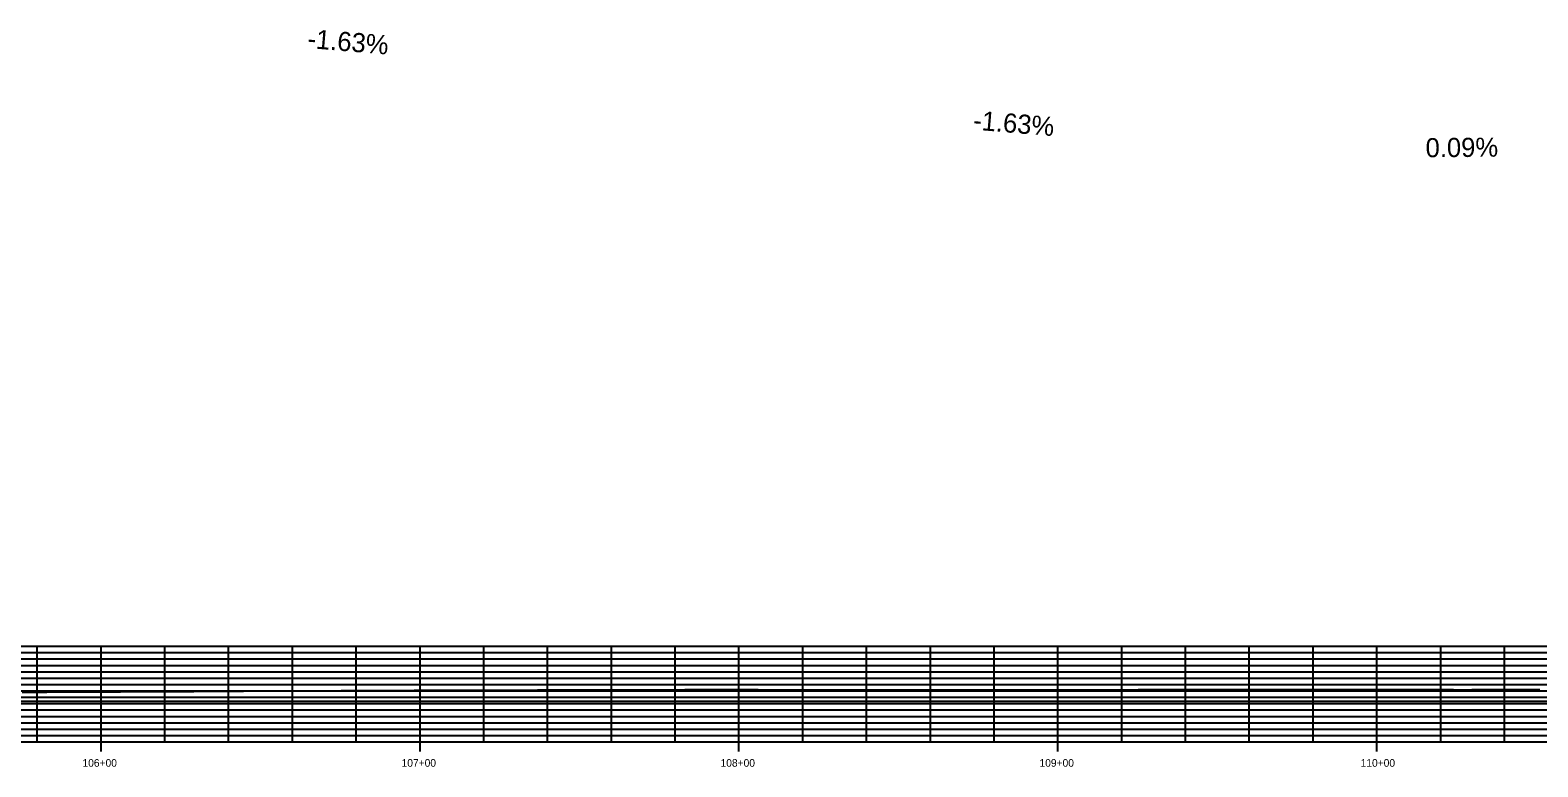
# Model space of a CAD drawing. Extents: x 1676565 to 1681112, y 227357 to 229815.
# Drawn here: x 1678745.1 to 1679217.8, y 229581 to 229812.1 of the extents above; entities that cross this region are included whole.
import ezdxf

# ---------------------------------------------------------------- set-up
doc = ezdxf.new("R2010")
doc.units = 0
for name, color, linetype in [('R_Axis', 7, 'Continuous'), ('R_Axis Annot', 7, 'Continuous'), ('R_Exist Surface', 7, 'Continuous'), ('R_Grid', 7, 'Continuous'), ('R_Horz Alg Annot', 7, 'Continuous'), ('R_Water', 7, 'Continuous')]:
    doc.layers.add(name, color=color, linetype=linetype)

msp = doc.modelspace()

# ---------------------------------------------------------------- linework, layer by layer
at = {"layer": 'R_Axis'}
msp.add_line((1678167.31, 229588.83), (1681067.31, 229588.83), dxfattribs=at)
at = {"layer": 'R_Exist Surface'}
msp.add_lwpolyline([(1678742.59, 229604.41), (1678748.25, 229604.44), (1678750.02, 229604.45), (1678750.28, 229604.45), (1678757.97, 229604.49), (1678762.9, 229604.52), (1678764.24, 229604.52), (1678765.66, 229604.53), (1678773.36, 229604.56), (1678777.16, 229604.58), (1678777.99, 229604.58), (1678781.05, 229604.6), (1678788.74, 229604.64), (1678790.98, 229604.65), (1678791.72, 229604.65), (1678796.43, 229604.68), (1678804.13, 229604.72), (1678811.35, 229604.75), (1678811.82, 229604.75), (1678812.01, 229604.75), (1678819.51, 229604.8), (1678822.63, 229604.81), (1678823.09, 229604.81), (1678827.2, 229604.84), (1678834.9, 229604.88), (1678842.59, 229604.92), (1678844.34, 229604.93), (1678845.27, 229604.93), (1678850.28, 229604.95), (1678857.97, 229604.98), (1678865.43, 229605.01), (1678865.67, 229605.01), (1678866.64, 229605.01), (1678873.36, 229605.04), (1678876.61, 229605.05), (1678877.32, 229605.05), (1678881.05, 229605.06), (1678888.75, 229605.08), (1678892.08, 229605.09), (1678893.34, 229605.1), (1678896.44, 229605.1), (1678904.13, 229605.12), (1678907.73, 229605.13), (1678909.56, 229605.14), (1678911.82, 229605.14), (1678919.12, 229605.16), (1678919.52, 229605.16), (1678920.08, 229605.16), (1678927.21, 229605.18), (1678934.9, 229605.19), (1678939.1, 229605.19), (1678940.61, 229605.2), (1678941.35, 229605.2), (1678942.59, 229605.2), (1678950.29, 229605.21), (1678957.98, 229605.21), (1678963.39, 229605.21), (1678964.93, 229605.21), (1678965.67, 229605.21), (1678966.97, 229605.21), (1678973.36, 229605.21), (1678981.06, 229605.2), (1678985.03, 229605.2), (1678986.05, 229605.2), (1678988.75, 229605.2), (1678995.08, 229605.19), (1678996.44, 229605.19), (1678996.54, 229605.19), (1679004.14, 229605.18), (1679010.15, 229605.18), (1679011.83, 229605.18), (1679019.52, 229605.18), (1679024.54, 229605.17), (1679025.65, 229605.17), (1679026.38, 229605.17), (1679027.21, 229605.17), (1679034.91, 229605.18), (1679040.89, 229605.18), (1679041.93, 229605.18), (1679042.6, 229605.18), (1679050.29, 229605.18), (1679056.66, 229605.18), (1679057.98, 229605.18), (1679065.68, 229605.19), (1679068.68, 229605.19), (1679069.17, 229605.19), (1679077.55, 229605.19), (1679081.21, 229605.2), (1679082.12, 229605.2), (1679085.02, 229605.2), (1679092.49, 229605.22), (1679094.17, 229605.22), (1679099.96, 229605.23), (1679106.23, 229605.24), (1679106.37, 229605.24), (1679107.43, 229605.25), (1679108.64, 229605.25), (1679114.9, 229605.26), (1679122.37, 229605.26), (1679129.84, 229605.27), (1679130.56, 229605.27), (1679130.75, 229605.27), (1679137.32, 229605.27), (1679144.79, 229605.26), (1679145.9, 229605.26), (1679146.9, 229605.26), (1679152.26, 229605.25), (1679159.73, 229605.24), (1679161.81, 229605.24), (1679162.97, 229605.24), (1679167.2, 229605.23), (1679174.67, 229605.22), (1679177.76, 229605.22), (1679179.19, 229605.21), (1679182.14, 229605.21), (1679189.61, 229605.21), (1679191.33, 229605.21), (1679192.8, 229605.2), (1679197.08, 229605.21), (1679204.55, 229605.21), (1679204.93, 229605.21), (1679206.25, 229605.21), (1679212.02, 229605.22), (1679218.36, 229605.22)], dxfattribs=at)
at = {"layer": 'R_Grid'}
for p, q in [((1678167.31, 229618.83), (1681067.31, 229618.83)), ((1678167.31, 229618.83), (1681067.31, 229618.83)), ((1678747.31, 229588.83), (1678747.31, 229618.83)), ((1678767.31, 229588.83), (1678767.31, 229618.83)), ((1678787.31, 229588.83), (1678787.31, 229618.83)), ((1678807.31, 229588.83), (1678807.31, 229618.83)), ((1678827.31, 229588.83), (1678827.31, 229618.83)), ((1678847.31, 229588.83), (1678847.31, 229618.83)), ((1678867.31, 229588.83), (1678867.31, 229618.83)), ((1678887.31, 229588.83), (1678887.31, 229618.83)), ((1678907.31, 229588.83), (1678907.31, 229618.83)), ((1678927.31, 229588.83), (1678927.31, 229618.83)), ((1678947.31, 229588.83), (1678947.31, 229618.83)), ((1678967.31, 229588.83), (1678967.31, 229618.83)), ((1678987.31, 229588.83), (1678987.31, 229618.83)), ((1679007.31, 229588.83), (1679007.31, 229618.83)), ((1679027.31, 229588.83), (1679027.31, 229618.83)), ((1679047.31, 229588.83), (1679047.31, 229618.83)), ((1679067.31, 229588.83), (1679067.31, 229618.83)), ((1679087.31, 229588.83), (1679087.31, 229618.83)), ((1679107.31, 229588.83), (1679107.31, 229618.83)), ((1679127.31, 229588.83), (1679127.31, 229618.83)), ((1679147.31, 229588.83), (1679147.31, 229618.83)), ((1679167.31, 229588.83), (1679167.31, 229618.83)), ((1679187.31, 229588.83), (1679187.31, 229618.83)), ((1679207.31, 229588.83), (1679207.31, 229618.83)), ((1678167.31, 229616.83), (1681067.31, 229616.83)), ((1678167.31, 229614.83), (1681067.31, 229614.83)), ((1678167.31, 229612.83), (1681067.31, 229612.83)), ((1678167.31, 229610.83), (1681067.31, 229610.83)), ((1678167.31, 229608.83), (1681067.31, 229608.83)), ((1678167.31, 229606.83), (1681067.31, 229606.83)), ((1678167.31, 229604.83), (1681067.31, 229604.83)), ((1678167.31, 229602.83), (1681067.31, 229602.83)), ((1678167.31, 229600.83), (1681067.31, 229600.83)), ((1678167.31, 229598.83), (1681067.31, 229598.83)), ((1678167.31, 229596.83), (1681067.31, 229596.83)), ((1678167.31, 229594.83), (1681067.31, 229594.83)), ((1678167.31, 229592.83), (1681067.31, 229592.83)), ((1678167.31, 229590.83), (1681067.31, 229590.83)), ((1678767.31, 229585.83), (1678767.31, 229588.83)), ((1678867.31, 229585.83), (1678867.31, 229588.83)), ((1678967.31, 229585.83), (1678967.31, 229588.83)), ((1679067.31, 229585.83), (1679067.31, 229588.83)), ((1679167.31, 229585.83), (1679167.31, 229588.83))]:
    msp.add_line(p, q, dxfattribs=at)
at = {"layer": 'R_Water'}
msp.add_line((1681080.69, 229601.46), (1678154.35, 229601.46), dxfattribs=at)

# ---------------------------------------------------------------- texts
at = {"layer": 'R_Axis Annot'}
for s, p in [('106+00', (1678761.48, 229581.03)), ('107+00', (1678861.53, 229581.03)), ('108+00', (1678961.53, 229581.03)), ('109+00', (1679061.53, 229581.03)), ('110+00', (1679162.21, 229581.03))]:
    msp.add_text(s, height=2.4, dxfattribs=at).set_placement(p)
at = {"layer": 'R_Horz Alg Annot'}
for s, rotation, p in [('-1.63%', 355.2838, (1678831.85, 229806.49)), ('-1.63%', 355.2838, (1679040.57, 229780.9)), ('0.09%', 0.5156, (1679182.6, 229772.19))]:
    msp.add_text(s, height=6, rotation=rotation, dxfattribs=at).set_placement(p)

doc.saveas('drawing.dxf')
